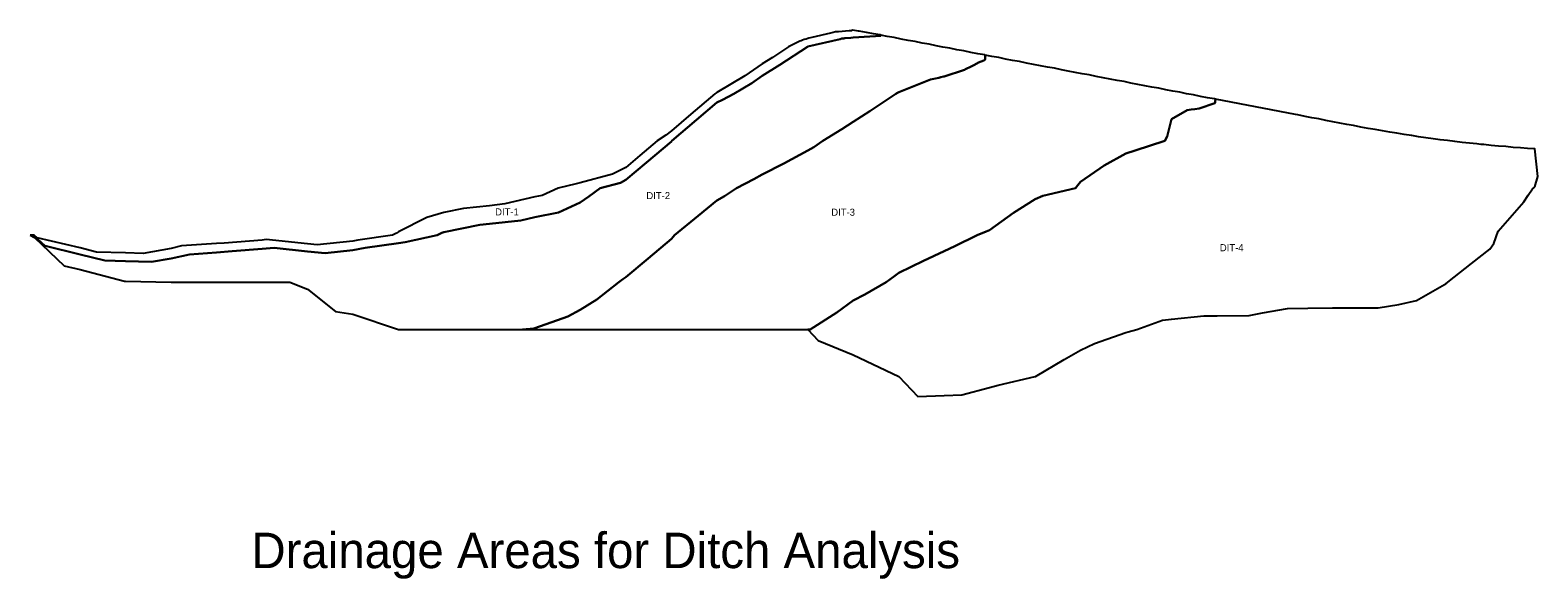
# Model space of a CAD drawing. Extents: x 2812 to 3876, y 2690 to 3077.
import ezdxf

# ---------------------------------------------------------------- set-up
doc = ezdxf.new("R2010")
doc.units = 0
doc.layers.add('SURVEY - DRAINAGE - Area Shapes', color=7, linetype='Continuous')
doc.layers.add('SURVEY - DRAINAGE - Area Shapes Text', color=7, linetype='Continuous')

msp = doc.modelspace()

# ---------------------------------------------------------------- linework, layer by layer
at = {"layer": 'SURVEY - DRAINAGE - Area Shapes'}
for p, q in [((3704.8, 3017.3), (3648.3, 3028.1)), ((3872, 2964.9), (3873, 2965.7)), ((3873, 2965.7), (3873.7, 2966.4)), ((3847.8, 2935.2), (3865.8, 2955.7))]:
    msp.add_line(p, q, dxfattribs=at)
for points in [[(3412.2, 3073.3), (3411.9, 3073.4), (3407, 3074.3), (3402.1, 3075.2), (3397.1, 3076), (3396.5, 3076), (3392.2, 3076.8), (3391.9, 3076.6), (3391.7, 3076.6), (3391.5, 3076.4), (3391.4, 3076.4), (3391.4, 3076.4), (3391.4, 3076.4), (3391.4, 3076.4), (3391.3, 3076.3), (3391.3, 3076.3), (3390, 3076.2), (3382.5, 3075.7), (3381, 3075.6), (3380.2, 3075.5), (3378.6, 3075.1), (3376.7, 3074.7), (3363.6, 3071.6), (3361.5, 3071.1), (3361.4, 3071.1), (3360.7, 3070.9), (3359.6, 3070.5)], [(2814.3, 2932.3), (2815.4, 2931.7), (2822.8, 2924.7), (2847.5, 2918.8), (2864.8, 2914.4), (2879.5, 2914), (2897.8, 2913.5), (2911.6, 2915.9), (2924.7, 2918.8), (2943.7, 2920.2), (2954.7, 2921), (2975.8, 2922.6), (2984.4, 2923.4), (3007.9, 2920.9), (3020.2, 2919.6), (3039.9, 2921.7), (3048.6, 2923.3), (3072, 2926.7), (3076.8, 2927.4), (3099.3, 2932.3), (3102.5, 2933.9), (3104.1, 2934.4), (3129.3, 2939.5), (3136.2, 2940.2), (3158.3, 2942.6), (3168.2, 2944.9), (3184.8, 2948.3), (3200.3, 2955.4), (3206.2, 2959.5), (3214.4, 2965.5), (3228.7, 2969.3), (3232.4, 2971.2), (3247, 2983.6), (3264.5, 2998.4), (3264.6, 2998.5), (3264.9, 2998.7), (3282.3, 3013.5), (3296.5, 3025.7), (3300.6, 3027.7), (3308.5, 3031.9), (3321.3, 3039.5), (3328.6, 3044.5), (3341, 3052.3), (3360.5, 3065.1), (3360.6, 3065.1), (3360.6, 3065.1), (3360.6, 3065.1), (3360.6, 3065.1), (3360.7, 3065.1), (3360.7, 3065.2), (3360.7, 3065.2), (3360.7, 3065.2), (3360.7, 3065.2), (3360.7, 3065.2), (3383.6, 3070.5), (3384.7, 3070.8), (3385.7, 3071), (3386.1, 3071), (3386.9, 3071.1), (3391.2, 3071.4), (3392.8, 3071.5), (3404.5, 3072.2), (3408.5, 3072.5), (3410.5, 3072.7), (3410.6, 3072.7), (3410.6, 3072.7), (3410.6, 3072.7), (3411.9, 3072.7), (3412.2, 3072.9), (3412.2, 3073.3)], [(3359.6, 3070.5), (3358.3, 3070.1), (3357.1, 3069.7), (3356.5, 3069.5), (3356, 3069.3), (3355.2, 3069), (3347.2, 3065.1), (3335.8, 3057.6), (3328.6, 3053.1), (3316.3, 3044.6), (3296.5, 3032.9), (3296, 3032.5), (3295.1, 3031.9), (3278.3, 3017.5), (3264.5, 3005.8), (3260.5, 3002.8), (3254.5, 2998.7), (3242.3, 2988.4), (3232.4, 2980), (3222.9, 2975.3), (3200.3, 2969.2), (3197.3, 2968.6), (3184.7, 2965.5), (3173.3, 2960.3), (3168.2, 2959.3), (3147, 2954.3)], [(3412.2, 3073.3), (3412.2, 3072.9), (3411.9, 3072.7), (3410.6, 3072.7), (3410.6, 3072.7), (3410.6, 3072.7), (3410.5, 3072.7), (3408.5, 3072.5), (3404.5, 3072.2), (3392.8, 3071.5), (3391.2, 3071.4), (3386.9, 3071.1), (3386.1, 3071), (3385.7, 3071), (3384.7, 3070.8), (3383.6, 3070.5), (3360.7, 3065.2), (3360.7, 3065.2), (3360.7, 3065.2), (3360.7, 3065.2), (3360.7, 3065.2), (3360.7, 3065.1), (3360.6, 3065.1), (3360.6, 3065.1), (3360.6, 3065.1), (3360.6, 3065.1), (3360.5, 3065.1), (3341, 3052.3), (3328.6, 3044.5), (3321.3, 3039.5), (3308.5, 3031.9), (3300.6, 3027.7), (3296.5, 3025.7), (3282.3, 3013.5), (3264.9, 2998.7)], [(3485.8, 3059.2), (3485.6, 3059.3), (3480.6, 3060.2), (3475.7, 3061.1), (3470.8, 3062.1), (3465.9, 3063), (3461, 3064), (3456.1, 3064.9), (3451.2, 3065.8), (3446.3, 3066.8), (3441.4, 3067.7), (3436.4, 3068.7), (3431.5, 3069.6), (3426.6, 3070.5), (3421.7, 3071.5), (3416.8, 3072.4), (3412.2, 3073.3)], [(2812.2, 2932.3), (2815.4, 2930.6), (2836.2, 2910.8), (2847.5, 2908.1), (2878.7, 2900), (2879.5, 2900), (2911.6, 2899.1), (2943.7, 2899.1), (2975.8, 2899.1), (2995.3, 2899.1), (3007.9, 2894.2), (3027.7, 2878.6), (3039.9, 2876.6), (3072, 2865.9), (3104.1, 2865.9), (3136.2, 2865.9), (3159.4, 2865.9), (3167.6, 2866.6), (3168.2, 2866.8), (3191.6, 2874.9), (3200.3, 2879.8), (3211.9, 2887.1), (3227.4, 2899.1), (3230.3, 2901.3), (3232.4, 2902.7), (3248.2, 2915.9), (3264.5, 2929.8), (3265.7, 2931.1), (3266.8, 2932.3), (3283.4, 2946), (3296.5, 2956.8), (3301.9, 2959.9), (3310.5, 2965.5), (3322.6, 2971.7), (3328.6, 2975.1), (3343.9, 2982.9), (3360.7, 2992.1), (3364.9, 2994.3), (3371.4, 2998.7), (3384.8, 3007), (3392.8, 3012.1), (3404.5, 3019.8), (3422.8, 3031.9), (3424.1, 3032.7), (3424.9, 3033), (3447.2, 3041.9), (3453.1, 3043.3), (3454.7, 3043.7), (3456.4, 3044.1), (3456.9, 3044.2), (3471.2, 3048.8), (3472.1, 3049.3), (3475.9, 3051.2), (3478.3, 3052.4)], [(3485.8, 3059.2), (3485.9, 3056.1), (3484.9, 3055.3), (3481.2, 3053.9), (3478.3, 3052.4), (3475.9, 3051.2), (3472.1, 3049.3), (3471.2, 3048.8), (3456.9, 3044.2), (3456.4, 3044.1), (3454.7, 3043.7), (3453.1, 3043.3), (3447.2, 3041.9), (3424.9, 3033), (3424.1, 3032.7), (3422.8, 3031.9), (3404.5, 3019.8), (3392.8, 3012.1), (3384.8, 3007), (3371.4, 2998.7), (3364.9, 2994.3), (3360.7, 2992.1), (3343.9, 2982.9), (3328.6, 2975.1), (3322.6, 2971.7)], [(3478.3, 3052.4), (3481.2, 3053.9), (3484.9, 3055.3), (3485.9, 3056.1), (3485.8, 3059.2)], [(3647.8, 3025.4), (3648, 3025.9), (3648, 3026), (3648, 3026.1), (3648, 3026.1), (3648.1, 3026.4), (3648.3, 3028.1), (3647.6, 3028.3), (3642.7, 3029.2), (3637.8, 3030.1), (3632.9, 3031.1), (3628, 3032), (3623.1, 3033), (3618.2, 3033.9), (3613.2, 3034.8), (3608.3, 3035.8), (3603.4, 3036.7), (3598.5, 3037.6), (3593.6, 3038.6), (3588.7, 3039.5), (3583.8, 3040.5), (3578.9, 3041.4), (3574, 3042.3), (3569, 3043.3), (3564.1, 3044.2), (3559.2, 3045.2), (3554.3, 3046.1), (3549.4, 3047), (3544.5, 3048), (3539.6, 3048.9), (3534.7, 3049.9), (3529.8, 3050.8), (3524.8, 3051.7), (3519.9, 3052.7), (3515, 3053.6), (3510.1, 3054.6), (3505.2, 3055.5), (3500.3, 3056.4), (3495.4, 3057.4), (3490.5, 3058.3), (3485.8, 3059.2)], [(3360.7, 2865.9), (3362.5, 2865.9), (3381.2, 2877.9), (3392.8, 2886.2), (3401, 2890.6), (3416.1, 2899.1), (3421.1, 2903), (3424.9, 2905.8), (3442.4, 2914.2), (3456.9, 2921), (3464.4, 2924.6), (3480.2, 2932.3), (3486.6, 2934.8), (3489, 2935.9), (3505.8, 2948.1), (3521.1, 2957.7), (3526.5, 2960), (3549.5, 2965.5), (3551.2, 2967.5), (3553.2, 2970), (3569.8, 2981.4), (3585.2, 2989.8), (3591.6, 2992.1), (3612.5, 2998.7), (3614.2, 3001.9), (3617.3, 3014), (3628.3, 3020.5), (3631.1, 3020.8), (3633.8, 3021.2), (3636.8, 3021.5), (3647.8, 3025.4)], [(3647.8, 3025.4), (3636.8, 3021.5), (3633.8, 3021.2), (3631.1, 3020.8), (3628.3, 3020.5), (3617.3, 3014), (3614.2, 3001.9), (3612.5, 2998.7), (3591.6, 2992.1), (3585.2, 2989.8), (3569.8, 2981.4), (3553.2, 2970), (3551.2, 2967.5), (3549.5, 2965.5), (3526.5, 2960), (3521.1, 2957.7), (3505.8, 2948.1), (3489, 2935.9), (3486.6, 2934.8), (3480.2, 2932.3), (3464.4, 2924.6), (3456.9, 2921), (3442.4, 2914.2), (3424.9, 2905.8), (3421.1, 2903), (3416.1, 2899.1), (3401, 2890.6)], [(3648.3, 3028.1), (3648.1, 3026.4), (3648, 3026.1), (3648, 3026.1), (3648, 3026), (3648, 3025.9), (3647.8, 3025.4)], [(3873.7, 2966.4), (3875.7, 2973.7), (3873.7, 2993.1), (3868.5, 2993.5), (3863.4, 2993.8), (3858.3, 2994.2), (3853.1, 2994.7), (3848, 2995.1), (3842.8, 2995.6), (3837.7, 2996.1), (3835.6, 2996.3), (3832.6, 2996.6), (3827.4, 2997.2), (3822.3, 2997.7), (3817.2, 2998.3), (3812.1, 2999), (3806.9, 2999.6), (3801.8, 3000.3), (3796.7, 3001), (3791.6, 3001.7), (3786.8, 3002.5), (3786.5, 3002.5), (3781.4, 3003.3), (3776.3, 3004.1), (3771.2, 3004.9), (3766.1, 3005.8), (3761, 3006.7), (3756, 3007.6), (3750.9, 3008.5), (3745.8, 3009.5), (3740.9, 3010.4), (3736, 3011.3), (3731.1, 3012.3), (3726.2, 3013.2), (3721.3, 3014.2), (3716.4, 3015.1), (3711.5, 3016), (3706.5, 3017), (3704.8, 3017.3)], [(3264.9, 2998.7), (3264.6, 2998.5), (3264.5, 2998.4), (3247, 2983.6), (3232.4, 2971.2), (3228.7, 2969.3), (3214.4, 2965.5), (3206.2, 2959.5), (3200.3, 2955.4), (3184.8, 2948.3), (3168.2, 2944.9), (3158.3, 2942.6), (3136.2, 2940.2), (3129.3, 2939.5), (3104.1, 2934.4), (3102.5, 2933.9), (3099.3, 2932.3), (3076.8, 2927.4), (3072, 2926.7), (3048.6, 2923.3), (3039.9, 2921.7), (3020.2, 2919.6), (3007.9, 2920.9), (2984.4, 2923.4), (2975.8, 2922.6), (2954.7, 2921), (2943.7, 2920.2), (2924.7, 2918.8), (2911.6, 2915.9), (2897.8, 2913.5), (2879.5, 2914), (2864.8, 2914.4), (2847.5, 2918.8), (2822.8, 2924.7), (2815.4, 2931.7), (2814.3, 2932.3)], [(3322.6, 2971.7), (3310.5, 2965.5), (3301.9, 2959.9), (3296.5, 2956.8), (3283.4, 2946), (3266.8, 2932.3), (3265.7, 2931.1), (3264.5, 2929.8), (3248.2, 2915.9), (3232.4, 2902.7), (3230.3, 2901.3), (3227.4, 2899.1), (3211.9, 2887.1), (3200.3, 2879.8), (3191.6, 2874.9), (3168.2, 2866.8), (3167.6, 2866.6), (3159.4, 2865.9)], [(3865.8, 2955.7), (3868.9, 2960.5), (3872, 2964.9)], [(3147, 2954.3), (3136.2, 2953.1), (3117.9, 2951.2), (3104.1, 2948.4), (3092, 2944.8), (3072, 2934.6), (3070.6, 2933.8), (3067.8, 2932.3), (3043.3, 2928.8), (3039.9, 2928.2), (3014.6, 2925.4), (3007.9, 2926.1), (2978.8, 2929.2), (2975.8, 2928.9), (2949, 2926.8), (2943.7, 2926.4), (2919, 2924.7), (2911.6, 2923), (2891.9, 2919.5), (2879.5, 2919.8), (2859, 2920.4), (2847.5, 2923.4), (2817.1, 2930.5), (2815.4, 2932.2), (2815.1, 2932.3), (2814.3, 2932.3)], [(2814.3, 2932.3), (2812.2, 2932.3)], [(3360.7, 2865.9), (3368.1, 2858.2), (3392.8, 2848.1), (3424.9, 2832.8), (3438.4, 2818.7), (3456.9, 2819.3), (3469.5, 2819.8), (3489, 2825), (3495, 2826.6), (3521.1, 2832.7), (3521.1, 2832.7), (3521.3, 2832.8), (3541.6, 2844.7), (3553.2, 2851.3), (3562.9, 2855.9), (3585.2, 2863.8), (3586.8, 2864.3), (3592.9, 2865.9), (3611, 2872.4), (3617.3, 2873.2), (3640.1, 2875.5), (3649.4, 2875.5), (3672.1, 2875.6), (3681.5, 2877.6), (3699.2, 2880.7), (3713.5, 2880.9), (3730.9, 2881.1), (3745.6, 2881.1), (3763, 2881.1), (3777.7, 2883.4), (3790.1, 2886.3), (3809.8, 2897.5), (3810.7, 2898.1), (3812.2, 2899.1), (3829, 2912.4), (3841.9, 2922.5), (3844.6, 2926.5), (3847.8, 2935.2)], [(3401, 2890.6), (3392.8, 2886.2), (3381.2, 2877.9), (3362.5, 2865.9), (3360.7, 2865.9)], [(3159.4, 2865.9), (3168.2, 2865.9), (3200.3, 2865.9), (3232.4, 2865.9), (3264.5, 2865.9), (3296.5, 2865.9), (3328.6, 2865.9), (3360.7, 2865.9)]]:
    msp.add_lwpolyline(points, dxfattribs=at)

# ---------------------------------------------------------------- texts
at = {"layer": 'SURVEY - DRAINAGE - Area Shapes Text'}
for s, height, p in [('DIT-2', 5, (3246.9, 2957.7)), ('DIT-1', 5, (3140.2, 2946.2)), ('DIT-3', 5, (3377.3, 2946)), ('DIT-4', 5, (3651.4, 2921)), ('Drainage Areas for Ditch Analysis', 25, (2968.3, 2697.7))]:
    msp.add_text(s, height=height, dxfattribs=at).set_placement(p)

doc.saveas('drawing.dxf')
